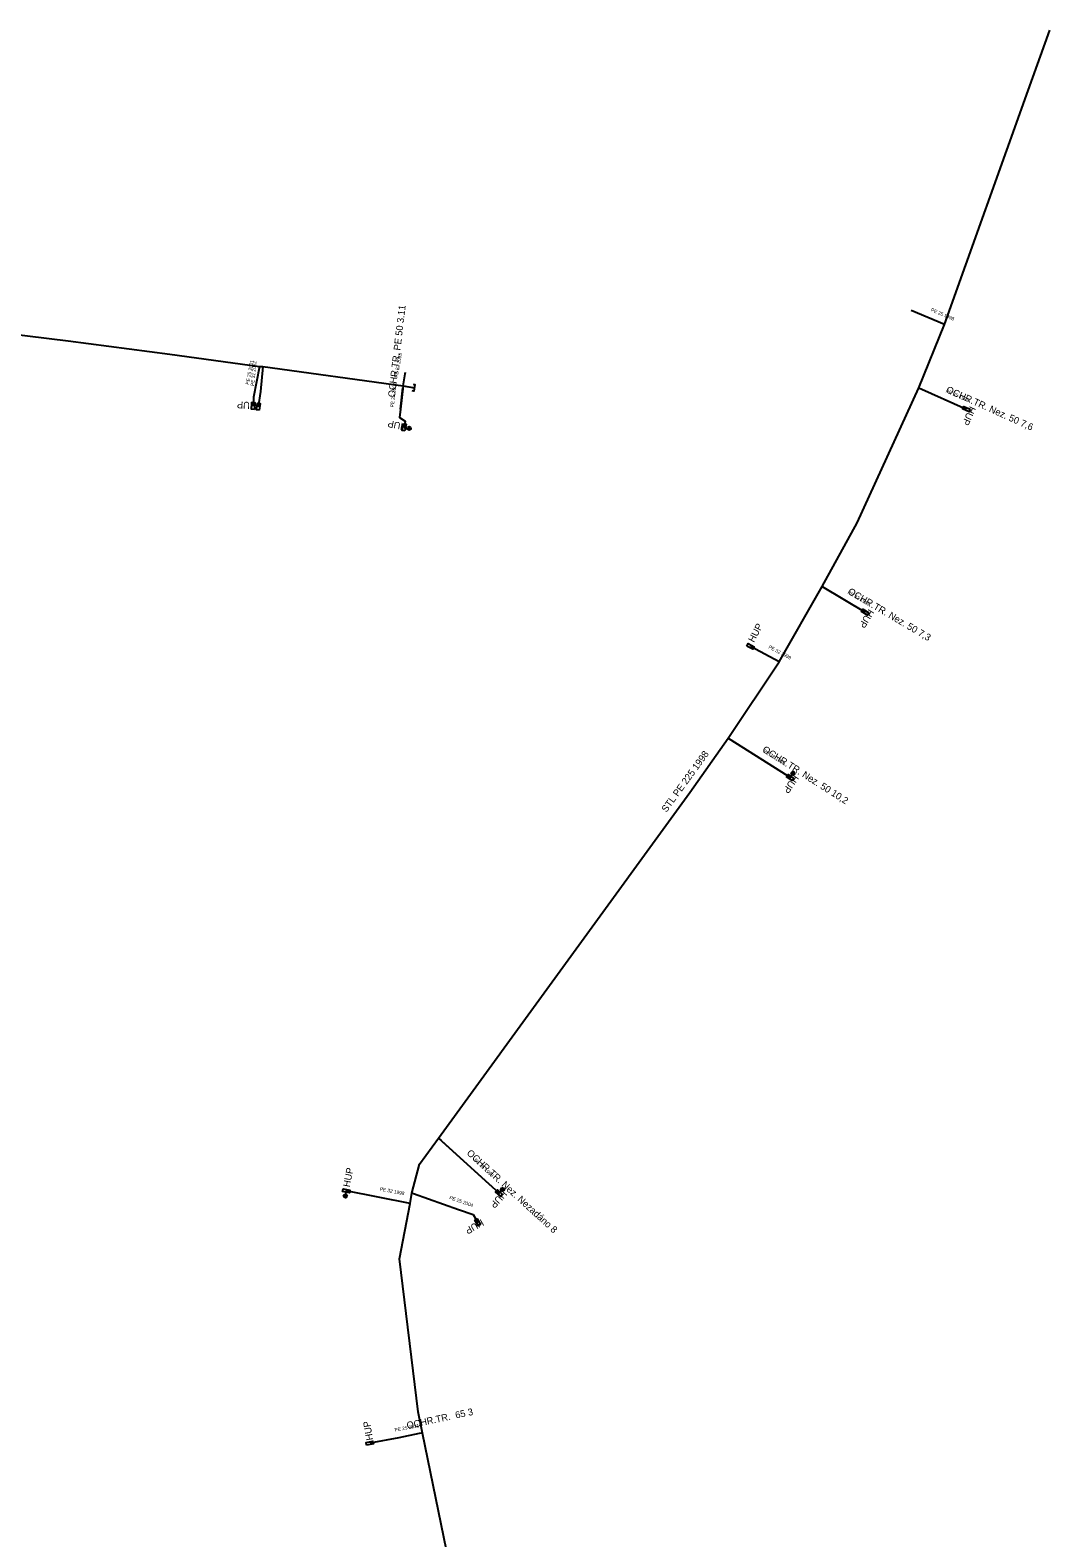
# Model space of a CAD drawing. Extents: x -741240 to -740302, y -1028024 to -1027535.
# Drawn here: x -740841.1 to -740693.2, y -1027754 to -1027535.4 of the extents above; entities that cross this region are included whole.
import ezdxf

# ---------------------------------------------------------------- set-up
doc = ezdxf.new("R2010")
doc.units = 0
for name, color, linetype in [('ST OP Chráni_ka - provoz', 7, 'Continuous'), ('ST Úsek p_ípojky - provoz', 7, 'Continuous'), ('ST Úsek plynovodu - provoz', 7, 'Continuous'), ('ST_HUP_22_23_popis', 7, 'Continuous'), ('Vrstva 1', 7, 'Continuous')]:
    doc.layers.add(name, color=color, linetype=linetype)

msp = doc.modelspace()

# ---------------------------------------------------------------- linework, layer by layer
at = {"layer": 'ST OP Chráni_ka - provoz'}
for points in [[(-740787.37, -1027590.37), (-740787.01, -1027587.28)], [(-740712.18, -1027587.27), (-740705.27, -1027590.38)], [(-740726.2, -1027616.11), (-740719.95, -1027619.8)], [(-740739.82, -1027638.08), (-740731.19, -1027643.56)], [(-740781.84, -1027696.05), (-740773.06, -1027704.06)], [(-740781.47, -1027696.39), (-740775.56, -1027701.78)], [(-740785.48, -1027704.11), (-740778.94, -1027706.43)], [(-740784.67, -1027738.89), (-740787.61, -1027739.52)]]:
    msp.add_lwpolyline(points, dxfattribs=at)
at = {"layer": 'ST Úsek p_ípojky - provoz'}
for points in [[(-740708.46, -1027578.09), (-740713.27, -1027576.07)], [(-740807.82, -1027584.22), (-740808.67, -1027588.65), (-740808.73, -1027589.9)], [(-740807.32, -1027584.22), (-740807.67, -1027587.8), (-740807.99, -1027590.03)], [(-740786.98, -1027587.02), (-740786.66, -1027585.26), (-740786.62, -1027585.03)], [(-740786.98, -1027587.02), (-740787.37, -1027590.37), (-740787.52, -1027591.58), (-740786.66, -1027592.14), (-740786.84, -1027593.02)], [(-740712.18, -1027587.27), (-740705.27, -1027590.38)], [(-740726.2, -1027616.11), (-740719.95, -1027619.8)], [(-740732.42, -1027627.01), (-740736.59, -1027624.78)], [(-740739.82, -1027638.08), (-740731.19, -1027643.56), (-740730.84, -1027643.8)], [(-740781.84, -1027696.05), (-740781.47, -1027696.39), (-740775.56, -1027701.78), (-740773.06, -1027704.06)], [(-740785.95, -1027705.54), (-740795.22, -1027703.72)], [(-740785.73, -1027704.03), (-740785.48, -1027704.11), (-740778.94, -1027706.43), (-740776.8, -1027707.14), (-740776.15, -1027708.27)], [(-740784.18, -1027738.81), (-740784.67, -1027738.89), (-740787.61, -1027739.52), (-740791.82, -1027740.29)]]:
    msp.add_lwpolyline(points, dxfattribs=at)
at = {"layer": 'ST Úsek plynovodu - provoz'}
for points in [[(-740779.14, -1027763.73), (-740779.53, -1027761.46), (-740784.18, -1027738.81), (-740784.78, -1027735.73), (-740787.5, -1027713.55), (-740785.95, -1027705.54), (-740785.73, -1027704.03), (-740784.6, -1027699.85), (-740781.84, -1027696.05), (-740745.38, -1027645.94), (-740739.82, -1027638.08), (-740732.42, -1027627.01), (-740726.2, -1027616.11), (-740721.12, -1027606.85), (-740712.18, -1027587.27), (-740708.46, -1027578.09), (-740696.29, -1027544.18), (-740693.16, -1027535.44)], [(-740989.01, -1027578.89), (-740987.88, -1027577.86), (-740985.2, -1027577.52), (-740963.53, -1027576.78), (-740951.66, -1027576.28), (-740943.13, -1027576.13), (-740927.11, -1027575.63), (-740912.67, -1027575.42), (-740900.63, -1027575.23), (-740884.87, -1027574.8), (-740877.38, -1027575.17), (-740872.34, -1027575.88), (-740853.69, -1027578.27), (-740835.56, -1027580.46), (-740820.8, -1027582.43), (-740807.82, -1027584.22), (-740807.32, -1027584.22), (-740786.98, -1027587.02), (-740786.95, -1027587.02), (-740785.34, -1027587.29)]]:
    msp.add_lwpolyline(points, dxfattribs=at)
at = {"layer": 'Vrstva 1'}
for p, q in [((-740786.84, -1027593.02), (-740786.35, -1027593.12)), ((-740730.84, -1027643.8), (-740730.56, -1027643.38)), ((-740795.22, -1027703.72), (-740795.32, -1027704.21)), ((-740773.06, -1027704.06), (-740772.72, -1027703.69))]:
    msp.add_line(p, q, dxfattribs=at)
msp.add_lwpolyline([(-740785.5, -1027586.76), (-740785.26, -1027586.8), (-740785.42, -1027587.78), (-740785.67, -1027587.74)], dxfattribs=at)
for points in [[(-740808.56, -1027590.41), (-740808.96, -1027590.39), (-740808.9, -1027589.39), (-740808.5, -1027589.41)], [(-740807.86, -1027590.55), (-740808.26, -1027590.49), (-740808.12, -1027589.5), (-740807.72, -1027589.56)], [(-740704.73, -1027590.4), (-740704.89, -1027590.77), (-740705.81, -1027590.36), (-740705.65, -1027589.99)], [(-740786.74, -1027593.55), (-740787.13, -1027593.47), (-740786.94, -1027592.49), (-740786.55, -1027592.57)], [(-740719.42, -1027619.89), (-740719.62, -1027620.23), (-740720.48, -1027619.71), (-740720.27, -1027619.37)], [(-740737.12, -1027624.72), (-740736.94, -1027624.37), (-740736.05, -1027624.84), (-740736.24, -1027625.19)], [(-740730.31, -1027643.91), (-740730.54, -1027644.24), (-740731.37, -1027643.69), (-740731.14, -1027643.35)], [(-740795.75, -1027703.82), (-740795.67, -1027703.43), (-740794.69, -1027703.62), (-740794.77, -1027704.01)], [(-740772.55, -1027704.25), (-740772.82, -1027704.54), (-740773.56, -1027703.87), (-740773.3, -1027703.58)], [(-740775.73, -1027708.6), (-740776.07, -1027708.8), (-740776.57, -1027707.94), (-740776.23, -1027707.74)], [(-740792.28, -1027740.57), (-740792.35, -1027740.18), (-740791.36, -1027740.01), (-740791.29, -1027740.4)]]:
    msp.add_lwpolyline(points, close=True, dxfattribs=at)
for centre, radius in [((-740786.1, -1027593.17), 0.249), ((-740786.14, -1027593.27), 0.0614), ((-740786.09, -1027593.07), 0.0614), ((-740730.42, -1027643.17), 0.249), ((-740730.52, -1027643.13), 0.0614), ((-740730.34, -1027643.24), 0.0614), ((-740772.56, -1027703.5), 0.249), ((-740772.64, -1027703.44), 0.0614), ((-740772.49, -1027703.58), 0.0614), ((-740795.36, -1027704.46), 0.249), ((-740795.46, -1027704.43), 0.0614), ((-740795.26, -1027704.47), 0.0614)]:
    msp.add_circle(centre, radius, dxfattribs=at)

# ---------------------------------------------------------------- texts
at = {"layer": 'ST OP Chráni_ka - provoz'}
for s, rotation, p in [('OCHR.TR. PE 50 3.11', 83.2816, (-740788.18, -1027588.71)), ('OCHR.TR. Nez. 50 7,6', 335.7688, (-740708.31, -1027587.91)), ('OCHR.TR. Nez. 50 7,3', 329.4424, (-740722.57, -1027617.09)), ('OCHR.TR. Nez. 50 10,2', 327.5847, (-740734.97, -1027639.97)), ('OCHR.TR. Nez. Nezadáno 8', 317.6396, (-740777.84, -1027698.35)), ('OCHR.TR.  65 3', 12.0948, (-740786.35, -1027738.23))]:
    msp.add_text(s, height=1, rotation=rotation, dxfattribs=at).set_placement(p)
at = {"layer": 'ST Úsek p_ípojky - provoz'}
for s, rotation, p in [('PE 25 1998', 337.2052, (-740710.48, -1027576.16)), ('PE 25 2001', 79.1385, (-740809.34, -1027586.86)), ('PE 32 2022', 84.4857, (-740808.6, -1027587.03)), ('PE 32 2003', 79.8528, (-740787.78, -1027585.85)), ('PE 25 2001', 83.2753, (-740788.35, -1027590.14)), ('PE 25 1998', 335.7757, (-740708.31, -1027587.91)), ('PE 32 1998', 329.4464, (-740722.57, -1027617.09)), ('PE 32 1998', 331.8577, (-740734.03, -1027625.01)), ('PE 32 1998', 327.5847, (-740734.79, -1027640.09)), ('PE 25 1999', 317.6348, (-740776.78, -1027699.32)), ('PE 32 1998', 348.8911, (-740790.39, -1027703.65)), ('PE 25 2004', 340.4684, (-740780.32, -1027704.88)), ('PE 25 2011', 10.3647, (-740788.17, -1027738.61))]:
    msp.add_text(s, height=0.5, rotation=rotation, dxfattribs=at).set_placement(p)
at = {"layer": 'ST Úsek plynovodu - provoz'}
msp.add_text('STL PE 225 1998', height=1, rotation=53.9604, dxfattribs=at).set_placement((-740748.78, -1027648.91))
at = {"layer": 'ST_HUP_22_23_popis'}
for rotation, p in [(177, (-740808.23, -1027589.4)), (246, (-740704.77, -1027589.88)), (169, (-740786.34, -1027592.52)), (239, (-740719.45, -1027619.3)), (62, (-740736.09, -1027624.28)), (236, (-740730.34, -1027643.3)), (79, (-740794.72, -1027703.22)), (228, (-740772.56, -1027703.56)), (210, (-740775.65, -1027707.77)), (100, (-740791.32, -1027739.79))]:
    msp.add_text('HUP', height=1, rotation=rotation, dxfattribs=at).set_placement(p)

doc.saveas('drawing.dxf')
